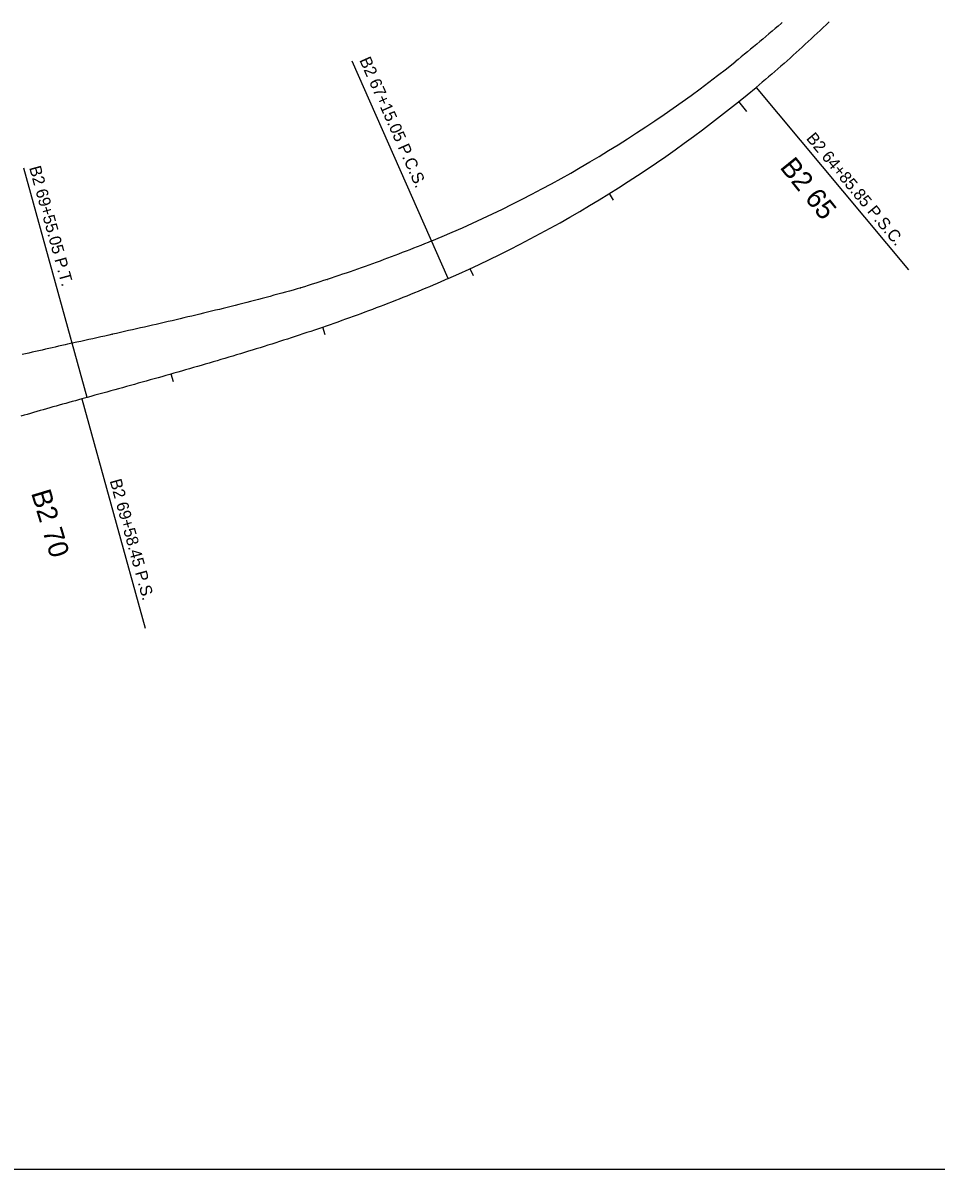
# Model space of a CAD drawing. Extents: x 7583978 to 7589962, y 550226 to 553847.
# Drawn here: x 7588753 to 7589329, y 550226 to 550949 of the extents above; entities that cross this region are included whole.
import ezdxf

# ---------------------------------------------------------------- set-up
doc = ezdxf.new("R2010")
doc.units = 0
for name, color, linetype in [('#plot_shape', 7, 'Continuous'), ('P_RDWY_ALIGN_Main', 7, 'Continuous'), ('P_RDWY_ALIGN_MainTx', 7, 'Continuous'), ('P_RDWY_ALIGN_Ramp', 7, 'Continuous'), ('P_RDWY_ALIGN_RampTic', 7, 'Continuous'), ('P_RDWY_ALIGN_RampTx', 7, 'Continuous')]:
    doc.layers.add(name, color=color, linetype=linetype)

msp = doc.modelspace()

# ---------------------------------------------------------------- linework, layer by layer
at = {"layer": '#plot_shape'}
msp.add_lwpolyline([(7588237.1, 551265.36), (7588237.1, 550226.04), (7589430.93, 550226.04), (7589430.93, 550741.48), (7589962.46, 551428.79), (7589291.08, 551428.4), (7589291.08, 551261.86)], close=True, dxfattribs=at)
at = {"layer": 'P_RDWY_ALIGN_Main'}
for p, q in [((7589229.27, 550946.98), (7589227.35, 550945.33)), ((7589231.17, 550948.64), (7589229.27, 550946.98)), ((7589231.84, 550949.22), (7589231.17, 550948.64)), ((7589221.6, 550940.4), (7589219.67, 550938.77)), ((7589223.52, 550942.04), (7589221.6, 550940.4)), ((7589225.44, 550943.68), (7589223.52, 550942.04)), ((7589227.35, 550945.33), (7589225.44, 550943.68)), ((7589213.86, 550933.92), (7589211.92, 550932.32)), ((7589215.8, 550935.53), (7589213.86, 550933.92)), ((7589217.74, 550937.15), (7589215.8, 550935.53)), ((7589219.67, 550938.77), (7589217.74, 550937.15)), ((7589204.1, 550925.96), (7589202.11, 550924.37)), ((7589206.06, 550927.54), (7589204.1, 550925.96)), ((7589208.02, 550929.12), (7589206.06, 550927.54)), ((7589209.97, 550930.72), (7589208.02, 550929.12)), ((7589211.92, 550932.32), (7589209.97, 550930.72)), ((7589006.28, 550809.58), (7589003.97, 550808.64)), ((7589008.59, 550810.52), (7589006.28, 550809.58)), ((7589011.01, 550811.52), (7589008.59, 550810.52)), ((7588990.02, 550803.15), (7588987.68, 550802.26)), ((7588992.35, 550804.05), (7588990.02, 550803.15)), ((7588993.54, 550804.51), (7588992.35, 550804.05)), ((7588994.68, 550804.95), (7588993.54, 550804.51)), ((7588997.01, 550805.86), (7588994.68, 550804.95)), ((7588999.33, 550806.78), (7588997.01, 550805.86)), ((7589001.65, 550807.71), (7588999.33, 550806.78)), ((7589003.97, 550808.64), (7589001.65, 550807.71)), ((7588968.87, 550795.34), (7588966.5, 550794.5)), ((7588971.23, 550796.18), (7588968.87, 550795.34)), ((7588973.59, 550797.03), (7588971.23, 550796.18)), ((7588975.95, 550797.89), (7588973.59, 550797.03)), ((7588978.3, 550798.75), (7588975.95, 550797.89)), ((7588980.65, 550799.62), (7588978.3, 550798.75)), ((7588983, 550800.49), (7588980.65, 550799.62)), ((7588985.34, 550801.37), (7588983, 550800.49)), ((7588987.68, 550802.26), (7588985.34, 550801.37)), ((7588947.48, 550787.99), (7588945.08, 550787.19)), ((7588949.86, 550788.78), (7588947.48, 550787.99)), ((7588952.25, 550789.58), (7588949.86, 550788.78)), ((7588954.63, 550790.39), (7588952.25, 550789.58)), ((7588957.01, 550791.2), (7588954.63, 550790.39)), ((7588959.39, 550792.02), (7588957.01, 550791.2)), ((7588961.76, 550792.84), (7588959.39, 550792.02)), ((7588964.14, 550793.67), (7588961.76, 550792.84)), ((7588966.5, 550794.5), (7588964.14, 550793.67)), ((7588926.06, 550781.15), (7588923.63, 550780.47)), ((7588927.67, 550781.61), (7588926.06, 550781.15)), ((7588928.27, 550781.8), (7588927.67, 550781.61)), ((7588930.68, 550782.55), (7588928.27, 550781.8)), ((7588933.09, 550783.31), (7588930.68, 550782.55)), ((7588935.49, 550784.08), (7588933.09, 550783.31)), ((7588937.89, 550784.85), (7588935.49, 550784.08)), ((7588940.29, 550785.63), (7588937.89, 550784.85)), ((7588942.69, 550786.41), (7588940.29, 550785.63)), ((7588945.08, 550787.19), (7588942.69, 550786.41)), ((7588899.18, 550773.89), (7588896.72, 550773.25)), ((7588901.63, 550774.53), (7588899.18, 550773.89)), ((7588904.08, 550775.17), (7588901.63, 550774.53)), ((7588906.53, 550775.82), (7588904.08, 550775.17)), ((7588908.98, 550776.47), (7588906.53, 550775.82)), ((7588911.43, 550777.13), (7588908.98, 550776.47)), ((7588913.87, 550777.79), (7588911.43, 550777.13)), ((7588916.31, 550778.45), (7588913.87, 550777.79)), ((7588918.75, 550779.12), (7588916.31, 550778.45)), ((7588921.19, 550779.8), (7588918.75, 550779.12)), ((7588923.63, 550780.47), (7588921.19, 550779.8)), ((7588869.59, 550766.45), (7588867.11, 550765.85)), ((7588872.06, 550767.06), (7588869.59, 550766.45)), ((7588874.53, 550767.66), (7588872.06, 550767.06)), ((7588877.01, 550768.27), (7588874.53, 550767.66)), ((7588879.48, 550768.88), (7588877.01, 550768.27)), ((7588881.95, 550769.5), (7588879.48, 550768.88)), ((7588884.41, 550770.12), (7588881.95, 550769.5)), ((7588886.88, 550770.74), (7588884.41, 550770.12)), ((7588889.34, 550771.36), (7588886.88, 550770.74)), ((7588891.8, 550771.99), (7588889.34, 550771.36)), ((7588894.26, 550772.62), (7588891.8, 550771.99)), ((7588896.72, 550773.25), (7588894.26, 550772.62)), ((7588839.76, 550759.4), (7588837.26, 550758.82)), ((7588842.25, 550759.98), (7588839.76, 550759.4)), ((7588844.75, 550760.55), (7588842.25, 550759.98)), ((7588847.24, 550761.13), (7588844.75, 550760.55)), ((7588849.72, 550761.72), (7588847.24, 550761.13)), ((7588852.21, 550762.3), (7588849.72, 550761.72)), ((7588854.7, 550762.89), (7588852.21, 550762.3)), ((7588857.18, 550763.48), (7588854.7, 550762.89)), ((7588859.67, 550764.07), (7588857.18, 550763.48)), ((7588862.15, 550764.66), (7588859.67, 550764.07)), ((7588864.63, 550765.26), (7588862.15, 550764.66)), ((7588867.11, 550765.85), (7588864.63, 550765.26)), ((7588807.23, 550752.02), (7588804.72, 550751.46)), ((7588809.74, 550752.58), (7588807.23, 550752.02)), ((7588812.25, 550753.14), (7588809.74, 550752.58)), ((7588814.75, 550753.71), (7588812.25, 550753.14)), ((7588817.26, 550754.27), (7588814.75, 550753.71)), ((7588819.77, 550754.84), (7588817.26, 550754.27)), ((7588822.27, 550755.4), (7588819.77, 550754.84)), ((7588824.77, 550755.97), (7588822.27, 550755.4)), ((7588827.27, 550756.54), (7588824.77, 550755.97)), ((7588829.77, 550757.11), (7588827.27, 550756.54)), ((7588832.27, 550757.68), (7588829.77, 550757.11)), ((7588834.77, 550758.25), (7588832.27, 550757.68)), ((7588837.26, 550758.82), (7588834.77, 550758.25)), ((7588773.57, 550744.51), (7588771.5, 550744.04)), ((7588775.64, 550744.97), (7588773.57, 550744.51)), ((7588777.71, 550745.44), (7588775.64, 550744.97)), ((7588779.77, 550745.9), (7588777.71, 550745.44)), ((7588781.23, 550746.23), (7588779.77, 550745.9)), ((7588787.12, 550747.53), (7588781.23, 550746.23)), ((7588789.63, 550748.09), (7588787.12, 550747.53)), ((7588792.15, 550748.65), (7588789.63, 550748.09)), ((7588794.67, 550749.21), (7588792.15, 550748.65)), ((7588797.18, 550749.77), (7588794.67, 550749.21)), ((7588799.69, 550750.33), (7588797.18, 550749.77)), ((7588802.21, 550750.9), (7588799.69, 550750.33)), ((7588804.72, 550751.46), (7588802.21, 550750.9)), ((7588754.76, 550740.2), (7588752.65, 550739.7)), ((7588756.86, 550740.69), (7588754.76, 550740.2)), ((7588758.97, 550741.18), (7588756.86, 550740.69)), ((7588761.07, 550741.67), (7588758.97, 550741.18)), ((7588763.16, 550742.15), (7588761.07, 550741.67)), ((7588765.25, 550742.62), (7588763.16, 550742.15)), ((7588767.34, 550743.1), (7588765.25, 550742.62)), ((7588769.42, 550743.57), (7588767.34, 550743.1)), ((7588771.5, 550744.04), (7588769.42, 550743.57))]:
    msp.add_line(p, q, dxfattribs=at)
msp.add_arc((7588707.55, 551543.66), 792.54, 292.51297, 308.61091, dxfattribs=at)
at = {"layer": 'P_RDWY_ALIGN_MainTx'}
for centre in [(7589229.27, 550946.98), (7589231.17, 550948.64), (7589221.6, 550940.4), (7589223.52, 550942.04), (7589225.44, 550943.68), (7589227.35, 550945.33), (7589213.86, 550933.92), (7589215.8, 550935.53), (7589217.74, 550937.15), (7589219.67, 550938.77), (7589204.1, 550925.96), (7589206.06, 550927.54), (7589208.02, 550929.12), (7589209.97, 550930.72), (7589211.92, 550932.32), (7589202.11, 550924.37), (7589215.38, 550908.24), (7589006.28, 550809.58), (7589008.59, 550810.52), (7589011, 550811.52), (7589011.01, 550811.52), (7588990.02, 550803.15), (7588992.35, 550804.05), (7588993.54, 550804.51), (7588994.68, 550804.95), (7588997.01, 550805.86), (7588999.33, 550806.78), (7589001.65, 550807.71), (7589003.97, 550808.64), (7588968.87, 550795.34), (7588971.23, 550796.18), (7588973.59, 550797.03), (7588975.95, 550797.89), (7588978.3, 550798.75), (7588980.65, 550799.62), (7588983, 550800.49), (7588985.34, 550801.37), (7588987.68, 550802.26), (7588947.48, 550787.99), (7588949.86, 550788.78), (7588952.25, 550789.58), (7588954.63, 550790.39), (7588957.01, 550791.2), (7588959.39, 550792.02), (7588961.76, 550792.84), (7588964.14, 550793.67), (7588966.5, 550794.5), (7588926.06, 550781.15), (7588927.67, 550781.61), (7588928.27, 550781.8), (7588930.68, 550782.55), (7588933.09, 550783.31), (7588935.49, 550784.08), (7588937.89, 550784.85), (7588940.29, 550785.63), (7588942.69, 550786.41), (7588945.08, 550787.19), (7589021.33, 550787.69), (7588899.18, 550773.89), (7588901.63, 550774.53), (7588904.08, 550775.17), (7588906.53, 550775.82), (7588908.98, 550776.47), (7588911.43, 550777.13), (7588913.87, 550777.79), (7588916.31, 550778.45), (7588918.75, 550779.12), (7588921.19, 550779.8), (7588923.63, 550780.47), (7588869.59, 550766.45), (7588872.06, 550767.06), (7588874.53, 550767.66), (7588877.01, 550768.27), (7588879.48, 550768.88), (7588881.95, 550769.5), (7588884.41, 550770.12), (7588886.88, 550770.74), (7588889.34, 550771.36), (7588891.8, 550771.99), (7588894.26, 550772.62), (7588896.72, 550773.25), (7588839.76, 550759.4), (7588842.25, 550759.98), (7588844.75, 550760.55), (7588847.24, 550761.13), (7588849.72, 550761.72), (7588852.21, 550762.3), (7588854.7, 550762.89), (7588857.18, 550763.48), (7588859.67, 550764.07), (7588862.15, 550764.66), (7588864.63, 550765.26), (7588867.11, 550765.85), (7588807.23, 550752.02), (7588809.74, 550752.58), (7588812.25, 550753.14), (7588814.75, 550753.71), (7588817.26, 550754.27), (7588819.77, 550754.84), (7588822.27, 550755.4), (7588824.77, 550755.97), (7588827.27, 550756.54), (7588829.77, 550757.11), (7588832.27, 550757.68), (7588834.77, 550758.25), (7588837.26, 550758.82), (7588773.57, 550744.51), (7588775.64, 550744.97), (7588777.71, 550745.44), (7588779.77, 550745.9), (7588781.23, 550746.23), (7588787.12, 550747.53), (7588789.63, 550748.09), (7588792.15, 550748.65), (7588794.67, 550749.21), (7588797.18, 550749.77), (7588799.69, 550750.33), (7588802.21, 550750.9), (7588804.72, 550751.46), (7588754.76, 550740.2), (7588756.86, 550740.69), (7588758.97, 550741.18), (7588761.07, 550741.67), (7588763.16, 550742.15), (7588765.25, 550742.62), (7588767.34, 550743.1), (7588769.42, 550743.57), (7588771.5, 550744.04), (7588790.32, 550711.78), (7588793.59, 550712.68)]:
    msp.add_circle(centre, 0.00187, dxfattribs=at)
at = {"layer": 'P_RDWY_ALIGN_Ramp'}
msp.add_line((7588793.59, 550712.68), (7588790.32, 550711.78), dxfattribs=at)
for points in [[(7589261.5, 550949.56), (7589259.63, 550947.78), (7589257.76, 550946.01), (7589255.88, 550944.24), (7589254, 550942.47), (7589252.11, 550940.71), (7589250.22, 550938.96), (7589248.33, 550937.21), (7589246.43, 550935.46), (7589244.52, 550933.72), (7589242.61, 550931.98), (7589240.7, 550930.25), (7589238.78, 550928.52), (7589236.86, 550926.8), (7589234.93, 550925.09), (7589233, 550923.38), (7589231.06, 550921.67), (7589229.12, 550919.97), (7589227.17, 550918.28), (7589225.22, 550916.59), (7589223.26, 550914.91), (7589221.3, 550913.24), (7589219.33, 550911.57), (7589217.36, 550909.9), (7589215.38, 550908.24)], [(7589021.33, 550787.69), (7589018.97, 550786.65), (7589016.6, 550785.62), (7589014.23, 550784.59), (7589011.86, 550783.57), (7589009.49, 550782.56), (7589007.11, 550781.56), (7589004.73, 550780.57), (7589002.34, 550779.58), (7588999.96, 550778.6), (7588997.57, 550777.62), (7588995.18, 550776.65), (7588992.78, 550775.69), (7588990.38, 550774.74), (7588987.98, 550773.79), (7588985.58, 550772.84), (7588983.18, 550771.91), (7588980.77, 550770.98), (7588978.36, 550770.06), (7588975.95, 550769.14), (7588973.53, 550768.23), (7588971.12, 550767.32), (7588968.7, 550766.42), (7588966.28, 550765.53), (7588963.85, 550764.64), (7588961.43, 550763.76), (7588959, 550762.88), (7588956.57, 550762.01), (7588954.14, 550761.15), (7588951.71, 550760.29), (7588949.27, 550759.43), (7588946.84, 550758.58), (7588944.4, 550757.74), (7588941.96, 550756.9), (7588939.52, 550756.06), (7588937.07, 550755.23), (7588934.63, 550754.41), (7588932.18, 550753.59), (7588929.73, 550752.77), (7588927.28, 550751.96), (7588924.83, 550751.16), (7588922.38, 550750.35), (7588919.92, 550749.56), (7588917.47, 550748.76), (7588915.01, 550747.97), (7588912.55, 550747.19), (7588910.09, 550746.41), (7588907.63, 550745.63), (7588905.17, 550744.86), (7588902.71, 550744.09), (7588900.24, 550743.32), (7588897.78, 550742.56), (7588895.31, 550741.8), (7588892.84, 550741.04), (7588890.37, 550740.29), (7588887.9, 550739.54), (7588885.43, 550738.8), (7588882.96, 550738.05), (7588880.49, 550737.31), (7588878.02, 550736.58), (7588875.54, 550735.84), (7588873.07, 550735.11), (7588870.59, 550734.38), (7588868.12, 550733.66), (7588865.64, 550732.94), (7588863.16, 550732.21), (7588860.68, 550731.5), (7588858.2, 550730.78), (7588855.72, 550730.07), (7588853.24, 550729.35), (7588850.76, 550728.64), (7588848.28, 550727.94), (7588845.8, 550727.23), (7588843.31, 550726.53), (7588840.83, 550725.82), (7588838.35, 550725.12), (7588835.86, 550724.42), (7588833.38, 550723.72), (7588830.89, 550723.03), (7588828.41, 550722.33), (7588825.92, 550721.64), (7588823.44, 550720.95), (7588820.95, 550720.25), (7588818.47, 550719.56), (7588815.98, 550718.87), (7588813.49, 550718.18), (7588811.01, 550717.49), (7588808.52, 550716.8), (7588806.03, 550716.12), (7588803.54, 550715.43), (7588801.06, 550714.74), (7588798.57, 550714.06), (7588796.08, 550713.37), (7588793.59, 550712.68)], [(7588790.32, 550711.78), (7588788.29, 550711.22), (7588786.26, 550710.66), (7588784.23, 550710.1), (7588782.2, 550709.53), (7588780.17, 550708.97), (7588778.14, 550708.41), (7588776.11, 550707.84), (7588774.09, 550707.28), (7588772.06, 550706.71), (7588770.03, 550706.14), (7588768.01, 550705.56), (7588765.98, 550704.99), (7588763.96, 550704.41), (7588761.93, 550703.83), (7588759.91, 550703.24), (7588757.89, 550702.65), (7588755.87, 550702.06), (7588753.85, 550701.47), (7588751.83, 550700.87)]]:
    msp.add_lwpolyline(points, dxfattribs=at)
msp.add_arc((7588690.64, 551536.42), 818.51, 293.82964, 309.87355, dxfattribs=at)
at = {"layer": 'P_RDWY_ALIGN_RampTic'}
for points in [[(7589209.46, 550893.04), (7589204.44, 550899.27)], [(7589125.6, 550837.15), (7589122.96, 550841.4)], [(7589037.14, 550789.36), (7589035.04, 550793.89)], [(7588943.78, 550752.24), (7588942.16, 550756.97)], [(7588847.99, 550722.65), (7588846.62, 550727.46)]]:
    msp.add_lwpolyline(points, dxfattribs=at)
at = {"layer": 'P_RDWY_ALIGN_RampTx'}
for points in [[(7589021.33, 550787.69), (7588960.73, 550924.9)], [(7589215.38, 550908.24), (7589311.54, 550793.13)], [(7588793.59, 550712.68), (7588753.68, 550857.28)], [(7588790.32, 550711.78), (7588830.22, 550567.18)]]:
    msp.add_lwpolyline(points, dxfattribs=at)

# ---------------------------------------------------------------- texts
at = {"layer": 'P_RDWY_ALIGN_RampTic'}
for s, rotation, p in [('B2 65', 308.88305, (7589229.91, 550857.72)), ('B2 70', 286.72454, (7588758.21, 550652.53))]:
    msp.add_text(s, height=12.5, rotation=rotation, dxfattribs=at).set_placement(p)
at = {"layer": 'P_RDWY_ALIGN_RampTx'}
for s, rotation, p in [('B2 67+15.05 P.C.S. ', 293.82964, (7588965.14, 550925.54)), ('B2 64+85.85 P.S.C. ', 309.87355, (7589246.62, 550875.92)), ('B2 69+55.05 P.T. ', 285.42964, (7588757.03, 550857.65)), ('B2 69+58.45 P.S. ', 285.42964, (7588807.82, 550660.18))]:
    msp.add_text(s, height=7.5, rotation=rotation, dxfattribs=at).set_placement(p)

doc.saveas('drawing.dxf')
